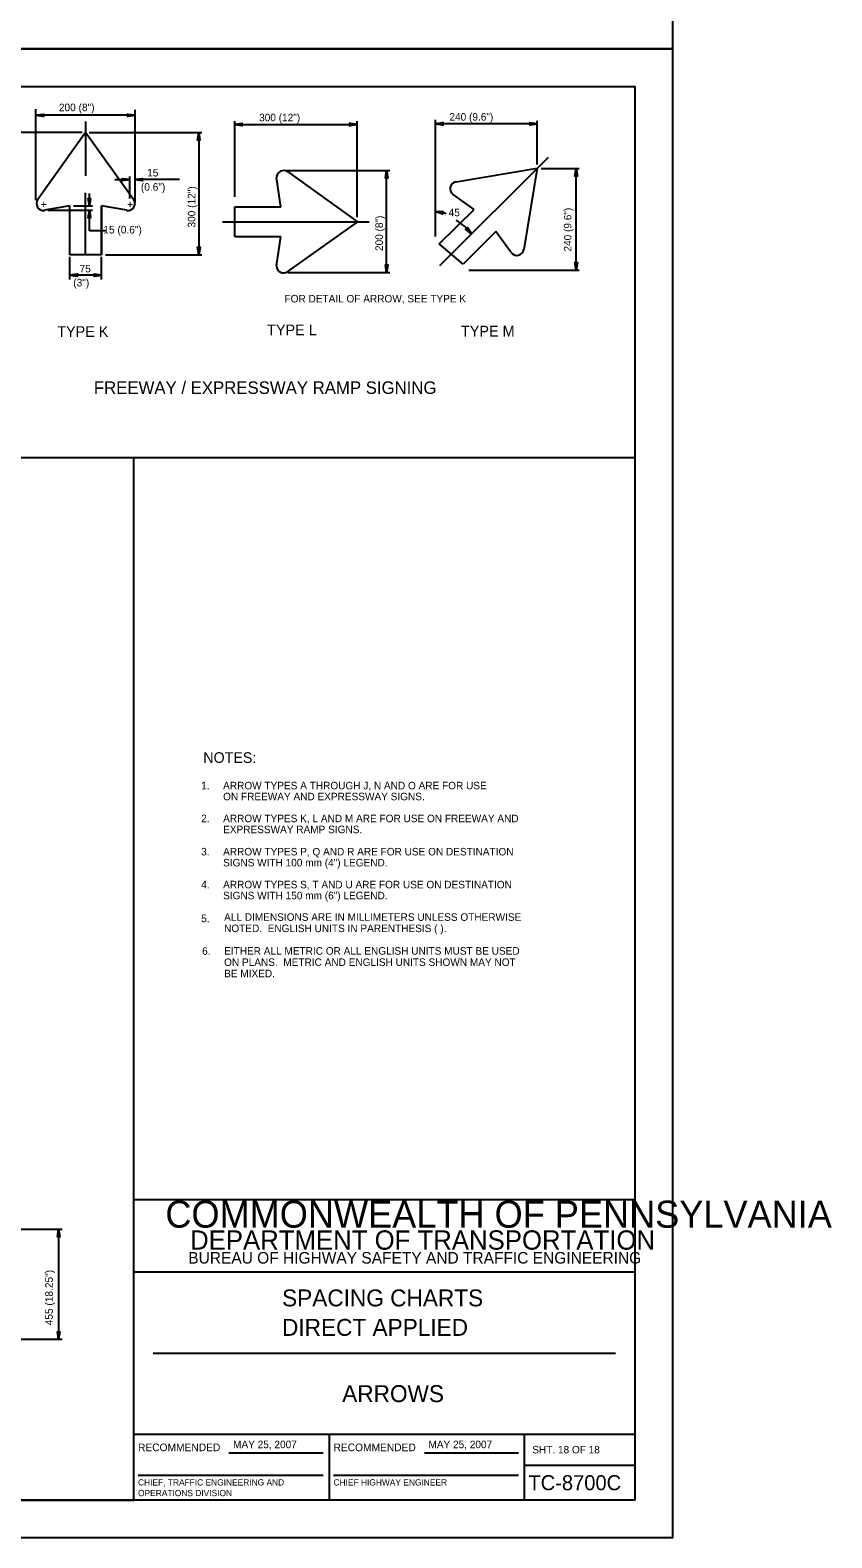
# Model space of a CAD drawing. Extents: x 637580 to 641849, y 297270 to 299646.
# Drawn here: x 641529 to 641849, y 298458 to 299059 of the extents above; entities that cross this region are included whole.
import ezdxf

# ---------------------------------------------------------------- set-up
doc = ezdxf.new("R2010")
doc.units = 0
for name, color, linetype in [('1', 7, 'Continuous'), ('2', 7, 'Continuous'), ('3', 7, 'Continuous'), ('XCS-GRID-HVGL', 7, 'Continuous')]:
    doc.layers.add(name, color=color, linetype=linetype)

# ---------------------------------------------------------------- blocks, each defined once
blk = doc.blocks.new('RARROW')
at = {"layer": '3'}
blk.add_lwpolyline([(-2.2695, 0.285), (-2.184875, 0.12075), (0, 0), (-2.2695, 0.285), (-2.38575, 0.384625), (0, 0), (-2.183125, -0.108), (-2.262875, -0.2705), (0, 0), (-2.38575, -0.379125), (-2.262875, -0.2705)], dxfattribs=at)

msp = doc.modelspace()

# ---------------------------------------------------------------- linework, layer by layer
at = {"layer": '1'}
for p, q in [((640984.31, 299036.63), (641770.31, 299036.63)), ((641770.31, 298472.63), (641770.31, 299036.63)), ((641570.31, 298472.63), (641570.31, 298592.63)), ((641570.31, 298592.63), (641770.31, 298592.63)), ((641770.31, 298563.63), (641570.31, 298563.63)), ((641578.06, 298531.31), (641762.56, 298531.31)), ((641570.31, 298499), (641770.31, 298499)), ((641648.31, 298499), (641648.31, 298472.63)), ((641726.19, 298472.63), (641726.19, 298499)), ((641608.24, 298491.57), (641645.87, 298491.57)), ((641686.24, 298491.57), (641723.87, 298491.57)), ((641571.99, 298482.68), (641645.87, 298482.68)), ((641649.99, 298482.68), (641723.87, 298482.68)), ((641726.19, 298486.63), (641770.31, 298486.63)), ((641770.31, 298472.63), (640984.31, 298472.63)), ((640984.31, 298472.63), (641570.31, 298472.63))]:
    msp.add_line(p, q, dxfattribs=at)
for points in [[(641770.31, 298888.5), (640984.31, 298888.5)], [(641570.31, 298592.63), (641570.31, 298888.5)]]:
    msp.add_lwpolyline(points, dxfattribs=at)
at = {"layer": '2'}
for p, q in [((641531.19, 298991.25), (641531.19, 299027.55)), ((641570.81, 299025.16), (641531.4, 299025.16)), ((641570.81, 298990.13), (641570.81, 299027.33)), ((641549.69, 299018.25), (641514.69, 299018.25)), ((641532.06, 298991.75), (641551.06, 299018.38)), ((641551.06, 299022.63), (641551.06, 299001)), ((641551.06, 299018.38), (641570.19, 298991.75)), ((641552.44, 299018.25), (641597.44, 299018.25)), ((641596.22, 299018.25), (641596.22, 298969.5)), ((641610.56, 298992.63), (641610.56, 299022.88)), ((641610.56, 299021.5), (641659.44, 299021.5)), ((641659.44, 298984.5), (641659.44, 299022.88)), ((641690.69, 298976.75), (641690.69, 299023.29)), ((641731.31, 299021.74), (641690.69, 299021.74)), ((641731.31, 299005.5), (641731.31, 299022.93)), ((641692.44, 298965.25), (641735.81, 299008.5)), ((641568.69, 298992), (641568.69, 299000.75)), ((641628.94, 298988.63), (641627.19, 299000.38)), ((641631.06, 299003.13), (641672.44, 299003.13)), ((641631.69, 299002.75), (641659.56, 298982.63)), ((641671.19, 298962.5), (641671.19, 299003.13)), ((641698.94, 298998.63), (641731.31, 299004)), ((641731.31, 299004), (641725.94, 298971.63)), ((641732.81, 299003.88), (641748.06, 299003.88)), ((641746.81, 298963.38), (641746.81, 299003.88)), ((641551.06, 298969.5), (641551.06, 298994.25)), ((641552.56, 298989), (641552.56, 298994)), ((641562.69, 298999.5), (641568.69, 298999.5)), ((641588.53, 298999.5), (641570.81, 298999.5)), ((641544.81, 298989), (641534.69, 298987.25)), ((641544.81, 298969.5), (641544.81, 298989)), ((641544.81, 298969.5), (641544.81, 298989)), ((641546.19, 298989), (641553.81, 298989)), ((641567.56, 298987.25), (641557.44, 298989)), ((641557.44, 298989), (641557.44, 298969.5)), ((641557.44, 298969.5), (641557.44, 298989)), ((641610.56, 298976.63), (641610.56, 298988.63)), ((641610.56, 298988.63), (641628.94, 298988.63)), ((641692.19, 298973.88), (641706.06, 298987.63)), ((641706.06, 298987.63), (641697.69, 298993.5)), ((641536.06, 298987.25), (641553.81, 298987.25)), ((641552.56, 298979), (641552.56, 298987.25)), ((641605.69, 298982.63), (641664.19, 298982.63)), ((641659.56, 298982.63), (641631.69, 298962.88)), ((641559.44, 298979), (641552.56, 298979)), ((641628.94, 298976.63), (641610.56, 298976.63)), ((641627.19, 298965.13), (641628.94, 298976.63)), ((641714.81, 298978.75), (641701.69, 298965.75)), ((641720.81, 298970.5), (641714.81, 298978.75)), ((641701.69, 298965.75), (641692.19, 298973.88)), ((641557.44, 298969.5), (641544.81, 298969.5)), ((641544.81, 298959.63), (641544.81, 298968.63)), ((641557.44, 298959.63), (641557.44, 298968.63)), ((641559.06, 298969.5), (641597.44, 298969.5)), ((641557.44, 298961.38), (641544.81, 298961.38)), ((641631.94, 298962.5), (641672.44, 298962.5)), ((641704.06, 298963.38), (641748.06, 298963.38)), ((641488.06, 298580.75), (641541.69, 298580.75)), ((641540.31, 298580.75), (641540.31, 298536.88)), ((641488.06, 298536.88), (641541.69, 298536.88))]:
    msp.add_line(p, q, dxfattribs=at)
for centre, radius, start, end in [((641630.08, 299000.29), 2.83, 54.40441, 180), ((641699.35, 298995.88), 2.83, 99.40376, 234.5287), ((641534.29, 298990), 2.83, 144.40376, 279.5287), ((641567.92, 298990), 2.83, 260.47321, 35.59303), ((641688.55, 298968.31), 18.65, 70.13194, 83.43124), ((641689.97, 298966.89), 18.65, 35.93254, 61.13668), ((641723.12, 298972.1), 2.83, 215.47321, 350.59303), ((641630.08, 298965.09), 2.83, 180, 305.5941)]:
    msp.add_arc(centre, radius, start, end, dxfattribs=at)
at = {"layer": 'XCS-GRID-HVGL'}
for points in [[(640944.31, 299645.63), (641785.31, 299645.63), (641785.31, 299051.63), (640944.31, 299051.63)], [(640944.31, 299051.63), (641785.31, 299051.63), (641785.31, 298457.63), (640944.31, 298457.63)]]:
    msp.add_lwpolyline(points, close=True, dxfattribs=at)

# ---------------------------------------------------------------- block references
at = {"layer": '2', "xscale": 1.2574347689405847}
for p, yscale, rotation in [((641531.4, 299025.16), 1.3092961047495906, 180), ((641596.22, 299018.25), 1.3092961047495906, 89.99999999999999), ((641610.56, 299021.5), 1.3092961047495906, 180), ((641690.69, 299021.74), 1.3092961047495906, 180), ((641570.81, 298999.5), 1.3092961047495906, 180), ((641671.19, 299003.13), 1.3092961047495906, 89.99999999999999), ((641746.81, 299003.88), 1.3092961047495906, 89.99999999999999), ((641552.56, 298989), 1.3092961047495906, -90.00000000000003), ((641552.56, 298987.25), 1.3092961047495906, 89.99999999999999), ((641690.68, 298986.83), 1.3092961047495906, 169.25034705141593), ((641705.07, 298977.83), 1.3092961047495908, -49.14095688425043), ((641596.22, 298969.5), 1.3092961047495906, -90.00000000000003), ((641671.19, 298962.5), 1.3092961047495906, -90.00000000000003), ((641746.81, 298963.38), 1.3092961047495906, -90.00000000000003), ((641544.81, 298961.38), 1.3092961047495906, 180), ((641540.31, 298580.75), 1.3092961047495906, 89.99999999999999), ((641540.31, 298536.88), 1.3092961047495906, -90.00000000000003)]:
    msp.add_blockref('RARROW', p, dxfattribs=dict(at, yscale=yscale, rotation=rotation))
at = {"layer": '2', "xscale": 1.2574347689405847, "yscale": 1.3092961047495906}
for p in [(641570.81, 299025.16), (641659.44, 299021.5), (641731.31, 299021.74), (641568.69, 298999.5), (641557.44, 298961.38)]:
    msp.add_blockref('RARROW', p, dxfattribs=at)

# ---------------------------------------------------------------- texts
at = {"layer": '1'}
for s, height, p in [('COMMONWEALTH OF PENNSYLVANIA', 10.7828, (641582.9, 298581.36)), ('DEPARTMENT OF TRANSPORTATION', 7.6837, (641592.76, 298572.61)), ('BUREAU OF HIGHWAY SAFETY AND TRAFFIC ENGINEERING', 4.6253, (641592.04, 298567.04)), ('SPACING CHARTS', 6.75, (641629.47, 298549.97)), ('DIRECT APPLIED', 6.75, (641629.45, 298538.22)), ('ARROWS', 6.75, (641653.47, 298511.78)), ('RECOMMENDED', 3.048, (641571.99, 298492.2)), ('RECOMMENDED', 3.048, (641649.99, 298492.2)), ('SHT. 18 OF 18', 3, (641729.32, 298491.31)), ('TC-8700C', 6, (641727.77, 298476.63)), ('OPERATIONS DIVISION', 2.5, (641571.99, 298474.26)), ('CHIEF, TRAFFIC ENGINEERING AND', 2.5, (641571.99, 298478.51)), ('CHIEF HIGHWAY ENGINEER', 2.5, (641649.99, 298478.51))]:
    msp.add_text(s, height=height, dxfattribs=at).set_placement(p)
at = {"layer": '2'}
for s, height, p in [('200 (8")', 3.022, (641540.4, 299026.8)), ('300 (12")', 3, (641620.32, 299022.77)), ('240 (9.6")', 3, (641696.27, 299023.03)), (' 15', 3.022, (641574.49, 299000.76)), ('(0.6")', 3.022, (641573.14, 298995.06)), ('+', 3, (641533.19, 298988.13)), ('+', 3, (641567.69, 298988.13)), ('45', 3.022, (641695.94, 298984.88)), (' 15 (0.6")', 3.022, (641557.03, 298978.01)), ('75', 3.022, (641548.65, 298962.47)), ('(3")', 3.022, (641546.14, 298956.89)), ('FOR DETAIL OF ARROW, SEE TYPE K', 3, (641630.44, 298950.5)), ('TYPE K', 4.3, (641539.74, 298936.72)), ('TYPE L', 4.3, (641623.49, 298937.37)), ('TYPE M', 4.3, (641700.86, 298936.9)), ('FREEWAY / EXPRESSWAY RAMP SIGNING', 5, (641554.37, 298914)), ('NOTES:', 4.25, (641598.03, 298766.8)), ('1. ', 3, (641597.19, 298756.25)), ('ARROW TYPES A THROUGH J, N AND O ARE FOR USE', 3, (641605.94, 298756.25)), ('ON FREEWAY AND EXPRESSWAY SIGNS.', 3, (641605.94, 298751.88)), ('2. ', 3, (641597.19, 298743.13)), ('ARROW TYPES K, L AND M ARE FOR USE ON FREEWAY AND', 3, (641605.94, 298743.13)), ('EXPRESSWAY RAMP SIGNS.', 3, (641605.94, 298738.75)), ('3. ', 3, (641597.19, 298729.88)), ('ARROW TYPES P, Q AND R ARE FOR USE ON DESTINATION', 3, (641605.94, 298729.88)), ('SIGNS WITH 100 mm (4") LEGEND.', 3, (641605.94, 298725.5)), ('4. ', 3, (641597.19, 298716.75)), ('ARROW TYPES S, T AND U ARE FOR USE ON DESTINATION', 3, (641605.94, 298716.75)), ('SIGNS WITH 150 mm (6") LEGEND.', 3, (641605.94, 298712.38)), ('5. ', 3, (641597.19, 298703.25)), ('ALL DIMENSIONS ARE IN MILLIMETERS UNLESS OTHERWISE', 3, (641606.34, 298703.79)), ('NOTED.  ENGLISH UNITS IN PARENTHESIS ( ).', 3, (641606.34, 298699.29)), ('6. ', 3, (641597.59, 298690.23)), ('EITHER ALL METRIC OR ALL ENGLISH UNITS MUST BE USED', 3, (641606.34, 298690.29)), ('ON PLANS.  METRIC AND ENGLISH UNITS SHOWN MAY NOT ', 3, (641606.34, 298685.79)), ('BE MIXED.', 3, (641606.34, 298681.29)), ('MAY 25, 2007', 3, (641609.93, 298493.39))]:
    msp.add_text(s, height=height, dxfattribs=at).set_placement(p)
for s, height, rotation, p in [('300 (12")', 3.022, 90, (641594.88, 298980.37)), ('240 (9.6")', 3, 90, (641744.93, 298970.79)), ('200 (8")', 3, 90, (641669.69, 298971.01)), ('455 (18.25")', 3.0217, 90, (641537.98, 298542.42)), ('MAY 25, 2007', 3, 360, (641687.88, 298493.39))]:
    msp.add_text(s, height=height, rotation=rotation, dxfattribs=at).set_placement(p)

doc.saveas('drawing.dxf')
